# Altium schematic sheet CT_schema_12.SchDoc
size 382 x 278 mm
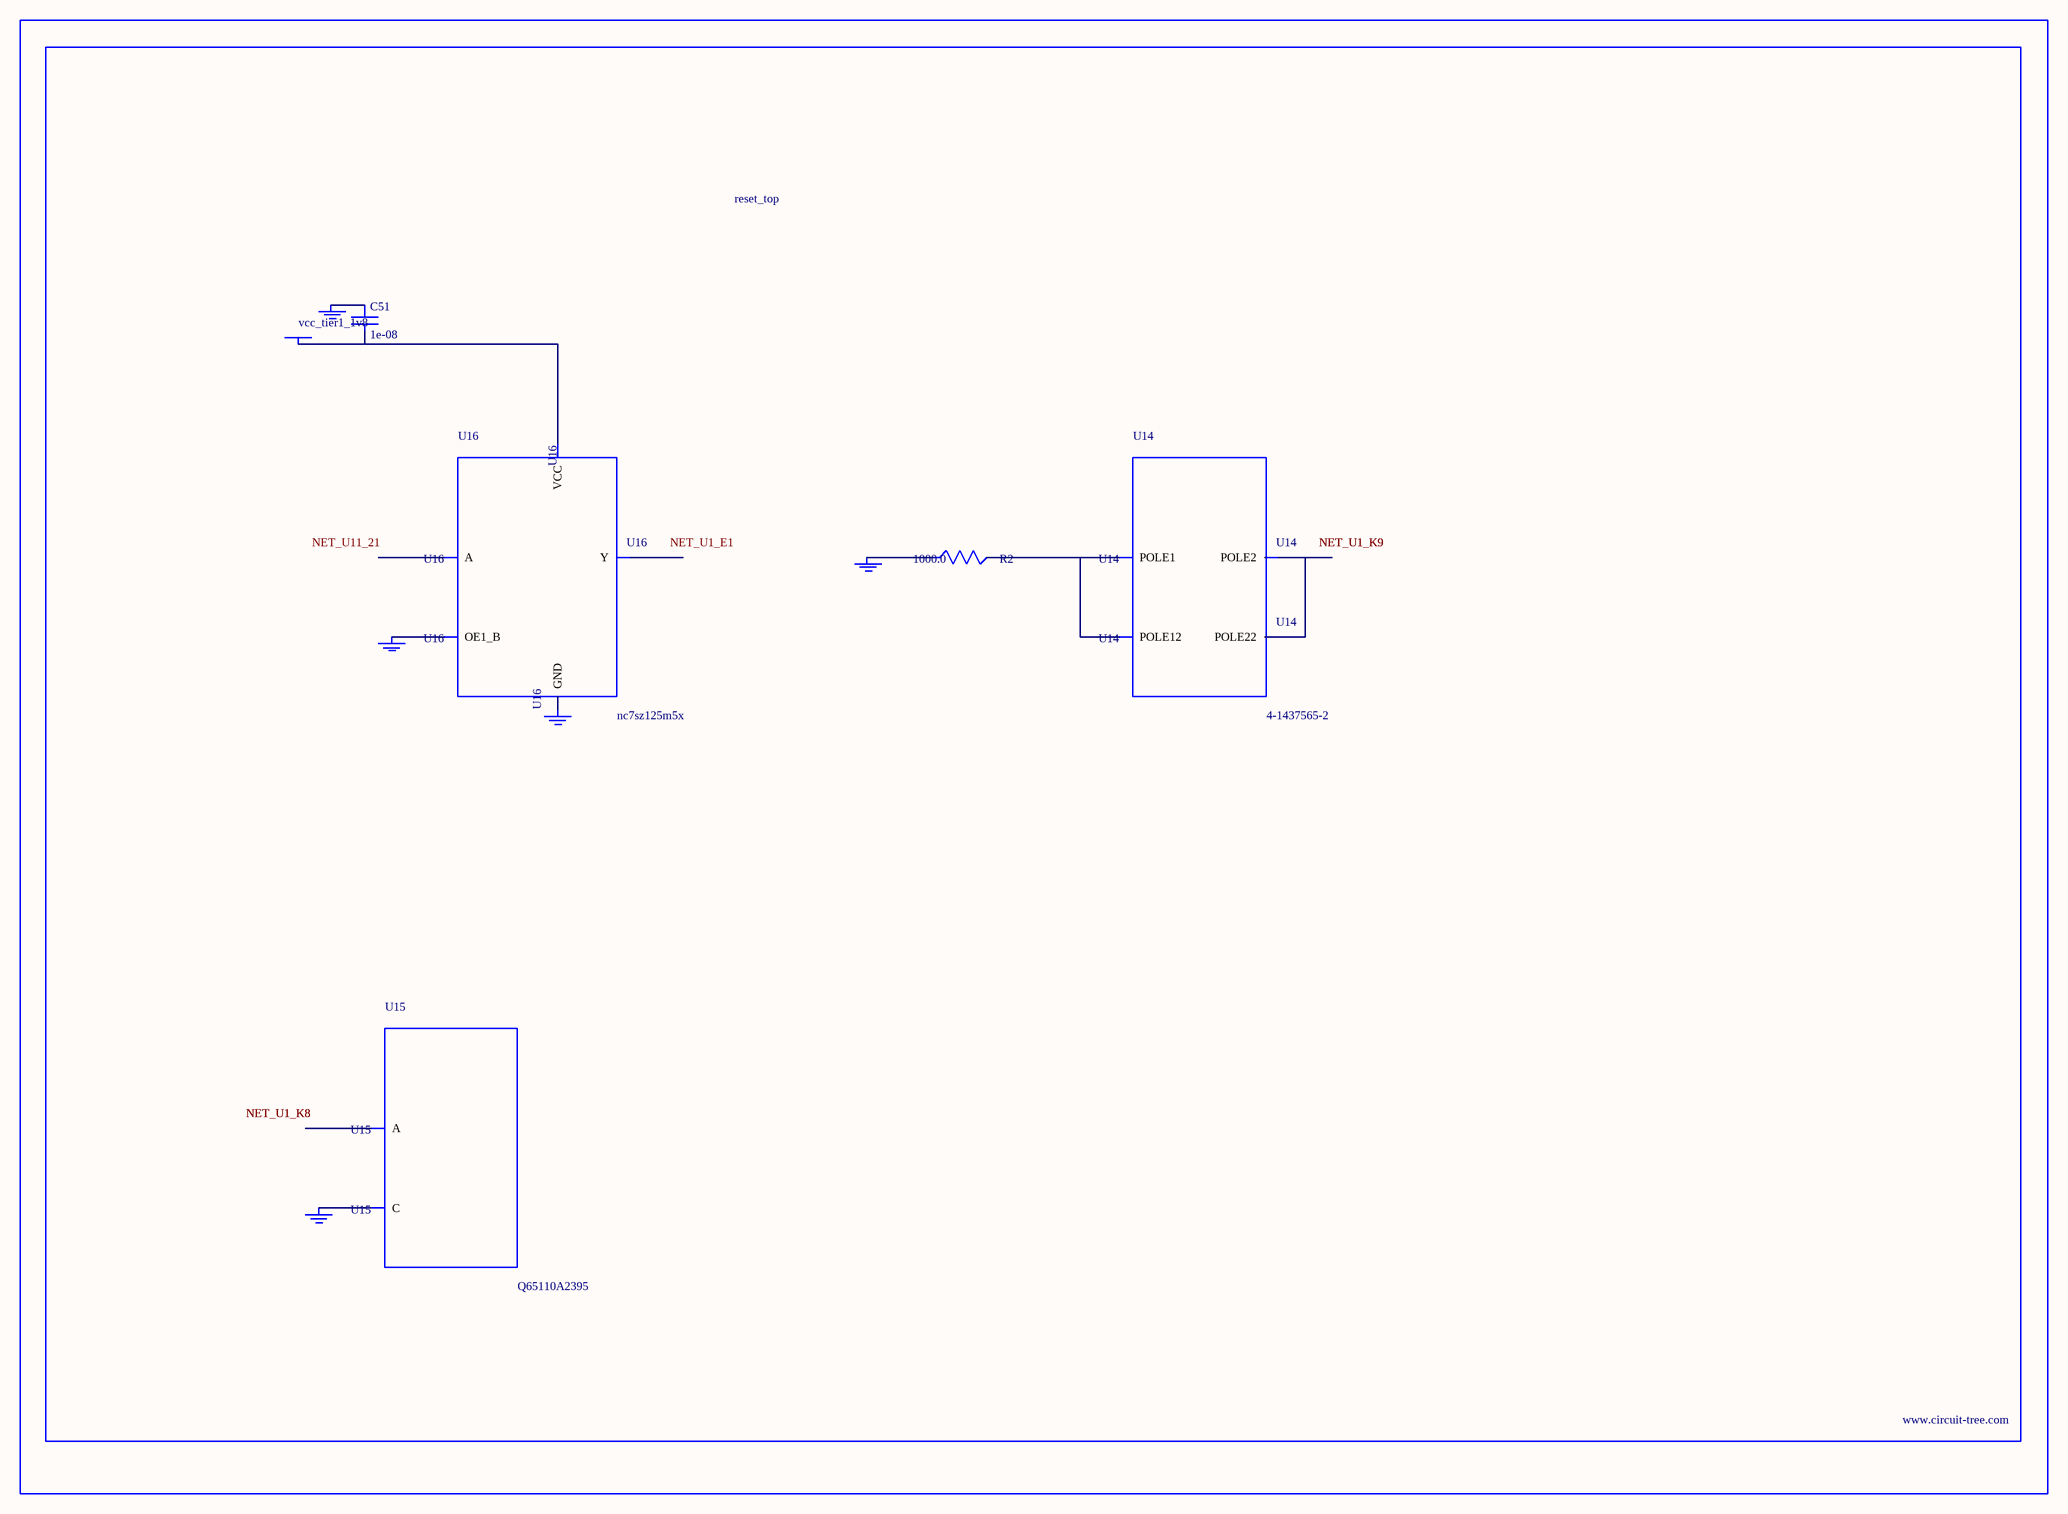
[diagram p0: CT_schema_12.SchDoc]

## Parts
BORDER11  (no value)
C51  1e-08  [C0402]
GND_INSTANCE_11_0  (no value)
GND_INSTANCE_11_1  (no value)
GND_INSTANCE_11_2  (no value)
GND_INSTANCE_11_3  (no value)
GND_INSTANCE_11_4  (no value)
POWER_INSTANCE_11_0  vcc_tier1_1v8
R2  1000.0  [R0603]
U14  4-1437565-2  [SW_4-1437565-2]
U15  Q65110A2395  [LGM67K-G1J2-24-Z]
U16  nc7sz125m5x  [NC7SZ125M5X]

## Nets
NetC51_1: C51.1 GND_INSTANCE_11_2.0(GND)
NetC51_2: C51.2 POWER_INSTANCE_11_0.0(PWR) U16.5(VCC)
NetGND_INSTANCE_11_0_0: GND_INSTANCE_11_0.0(GND) R2.1
NetGND_INSTANCE_11_1_0: GND_INSTANCE_11_1.0(GND) U15.C
NetGND_INSTANCE_11_3_0: GND_INSTANCE_11_3.0(GND) U16.1(OE1_B)
NetGND_INSTANCE_11_4_0: GND_INSTANCE_11_4.0(GND) U16.3(GND)
NetR2_2: R2.2 U14.1(POLE1) U14.2(POLE12)
NetU14_3: U14.3(POLE2) U14.4(POLE22)

Not connected (* = marked no-connect by the designer): U15 A; U16 2(A) 4(Y)

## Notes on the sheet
- Labels drawn without touching a wire or pin: NET_U1_E1, NET_U11_21

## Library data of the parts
BORDER11 = BORDER_PAGE11
C51 = C0402C103K3RAC
GND_INSTANCE_11_0-GND_INSTANCE_11_4 = GND
POWER_INSTANCE_11_0 = PWR
R2 = RC0603JR-071KL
